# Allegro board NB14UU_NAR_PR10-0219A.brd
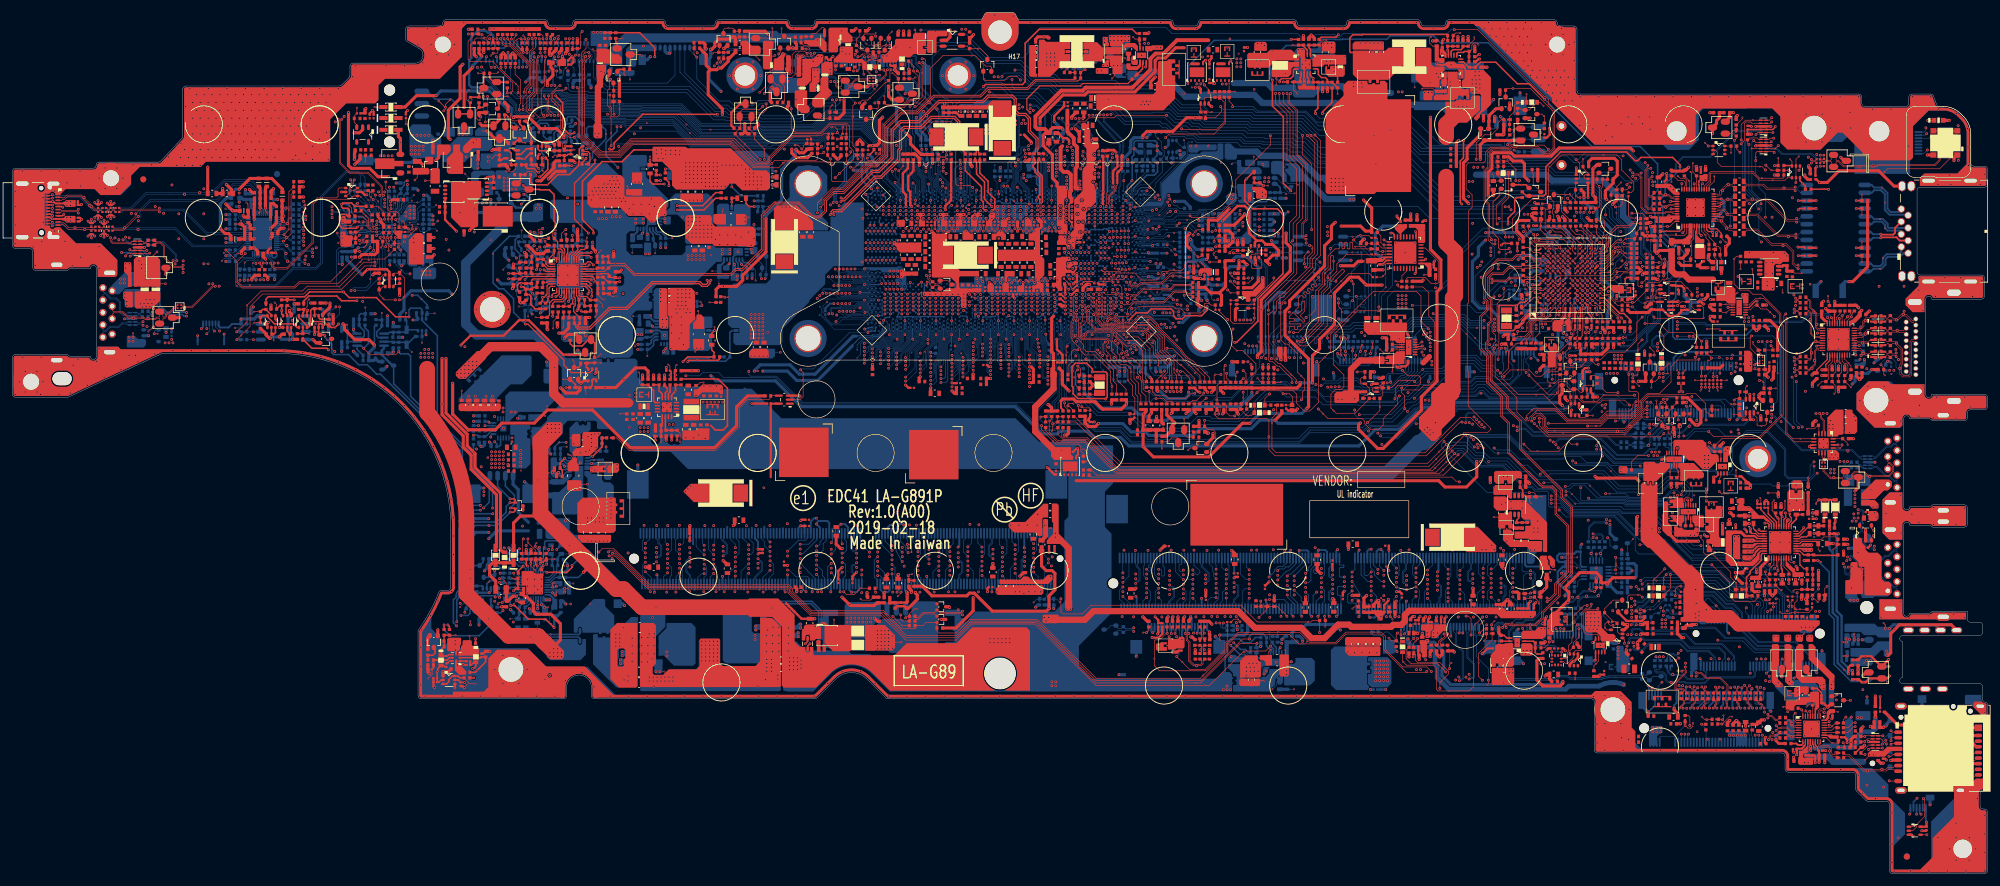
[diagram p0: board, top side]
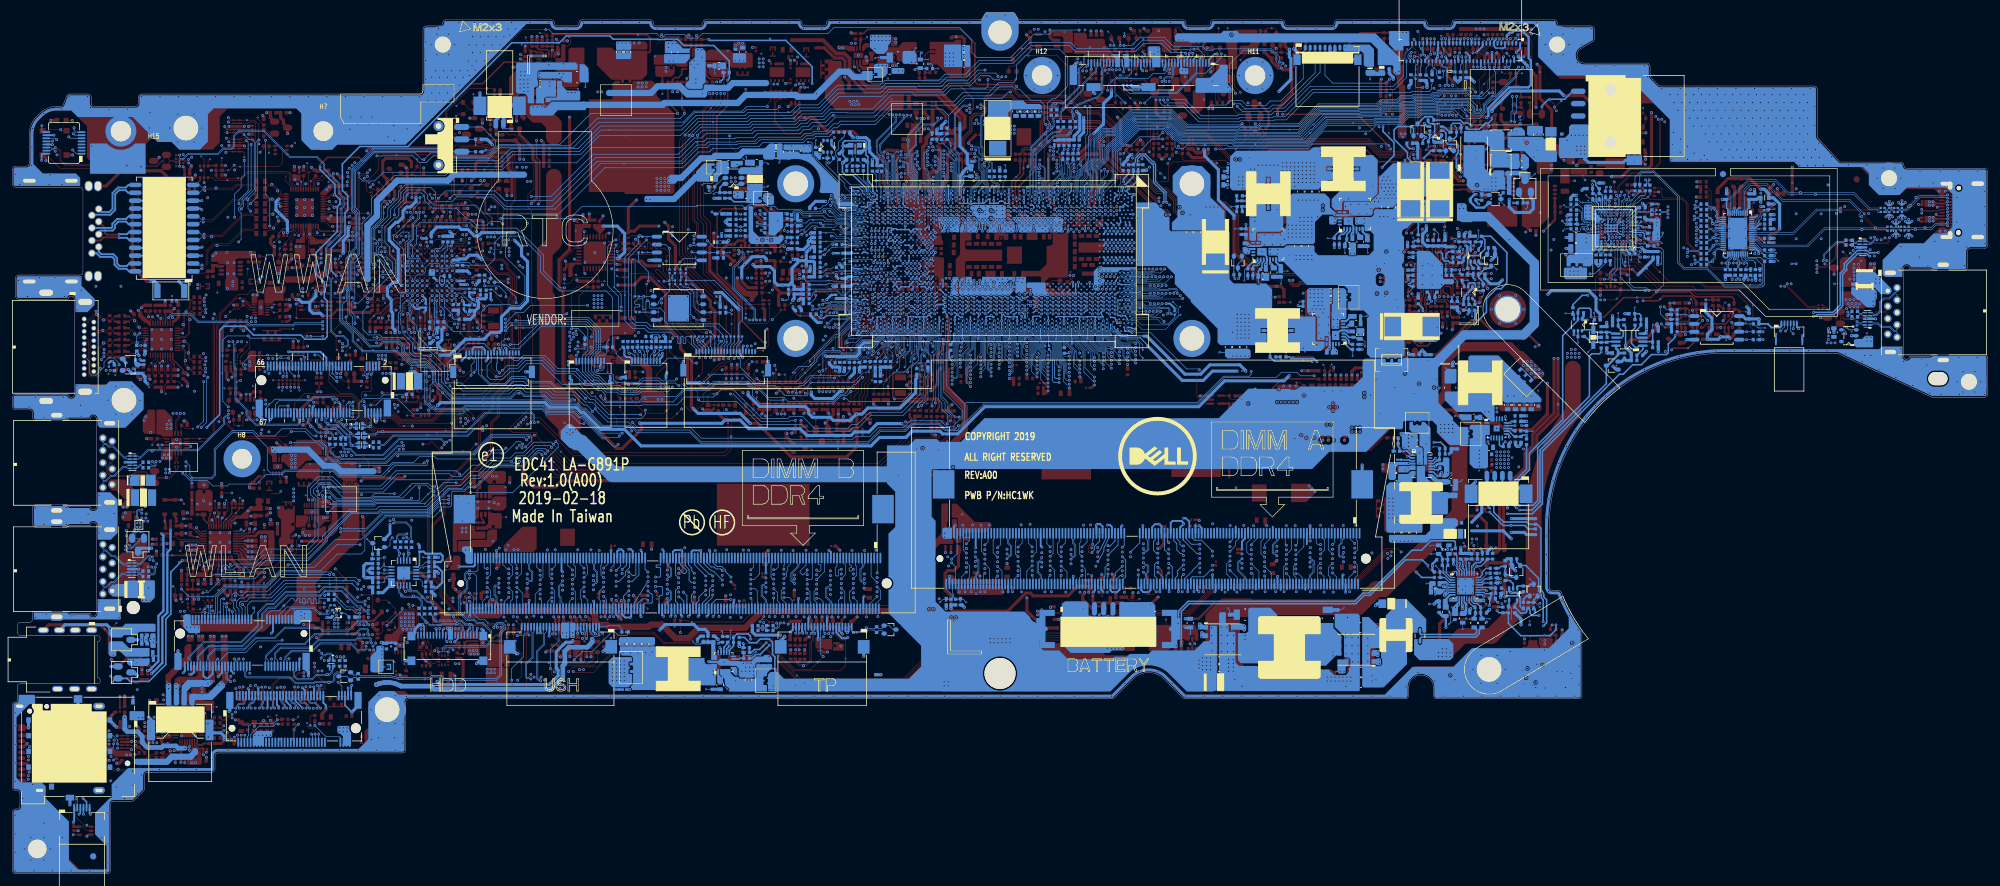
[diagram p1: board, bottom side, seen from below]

Outline 319.05 x 139.2 mm; copper layers: TOP, GND1, IN1, VCC, IN2, IN3, GND2, BOTTOM. Coordinates in mm from the lower left corner of the outline.

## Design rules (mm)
net group BC_CLK_ECE1117: nets BC_CLK_ECE1117 BC_DAT_ECE1117
net group CLK_TP_SIO_R: nets CLK_TP_SIO_R DAT_TP_SIO_R
net group CPU_DDPD_CTRL_CLK: nets CPU_DDPD_CTRL_CLK CPU_DDPD_CTRL_DATA
net group CPU_DP1_CTRL_CLK: nets CPU_DP1_CTRL_CLK CPU_DP1_CTRL_DATA
net group CPU_DP2_CTRL_CLK: nets CPU_DP2_CTRL_CLK CPU_DP2_CTRL_DATA
net group CPU_DP3_AUX: nets CPU_DP3_AUXN CPU_DP3_AUXP
net group CSI_ISL9538: nets CSIN_CHG CSIP_CHG
net group CSO_ISL9538: nets CSON_CHG CSOP_CHG
net group DDR_RESET: nets DDR_DRAMRST# DDR_DRAMRST#_R
net group DDRA_CKE: nets DDR_A_CKE0 DDR_A_CKE1
net group DDRALERT_10/10.5_20: nets DDR_A_ALERT# DDR_B_ALERT#
net group DIFFPAIR8: nets SML1_SMBCLK SML1_SMBDATA
net group DIFFPAIR9: nets MEM_SMBCLK MEM_SMBDATA
net group ESPI_CLK: nets ESPI_CLK ESPI_CLK_5105
net group HDMI_CLK_C: nets HDMI_CLKN_C HDMI_CLKP_C
net group HDMI_SCL_SINK: nets HDMI_SCL_SINK HDMI_SDA_SINK
net group HDMI_TX_0_C: nets HDMI_TX_N0_C HDMI_TX_P0_C
net group HDMI_TX_1_C: nets HDMI_TX_N1_C HDMI_TX_P1_C
net group HDMI_TX_2_C: nets HDMI_TX_N2_C HDMI_TX_P2_C
net group I2C1_SCK_TP: nets I2C1_SCK_TP I2C1_SDA_TP
net group ISH_I2C0_ACC_SCL: nets ISH_I2C0_ACC_SCL ISH_I2C1_ALS_SDA
net group PCIE_PRX_C_DTX_N12: nets PCIE_PRX_C_DTX_N12 PCIE_PRX_C_DTX_P12
net group PCIE_PTX_C_DRX_8: nets PCIE_PTX_C_DRX_N12 PCIE_PTX_C_DRX_P12
net group PCIE_PTX_DRX_12: nets PCIE_PTX_DRX_N12 PCIE_PTX_DRX_P12
net group PECI: nets PECI_EC PECI_EC_R
net group SATA_PRX_DTX_11: nets SATA_PRX_DTX_N11 SATA_PRX_DTX_P11
net group SATA_PTX_DRX_11: nets SATA_PTX_DRX_N11 SATA_PTX_DRX_P11
net group SD/MMCDAT0/RCLK: nets SD/MMCDAT0/RCLK+ SD/MMCDAT1/RCLK-
net group SD/MMCDAT0/RCLK+_R: nets SD/MMCDAT0/RCLK+_R SD/MMCDAT1/RCLK-_R
net group SD_UHS2_D0N: nets SD_UHS2_D0N SD_UHS2_D0P
net group SD_UHS2_D1N: nets SD_UHS2_D1N SD_UHS2_D1P
net group SML0_SMBCLK: nets SML0_SMBCLK SML0_SMBDATA
net group UART: nets UART_MISO UART_MOSI
net group VCC_SENSE_GT: nets VCC_SENSE_GT VSS_SENSE_GT
net group VCC_SENSE_IA: nets VCC_SENSE_IA VSS_SENSE_IA
net group VCC_SENSE_SA: nets VCC_SENSE_SA VSS_SENSE_SA
net group 5: nets ISH_I2C2_SCL ISH_I2C2_SCL_R ISH_I2C2_SDA ISH_I2C2_SDA_R ISH_UART0_CTS#_R ISH_UART0_RXD_R ISH_UART0_TXD_R PCH_3.3V_TS_EN PCH_BATLOW# PCH_CL_CLK1 PCH_CL_DATA1 PCH_CL_RST1# PCH_PRIM_EN PCH_RTCX1 PCH_RTCX2 PCH_RTCX2_R PCH_SPI_CS#0 PCH_SPI_CS#0_R1 PCH_SPI_CS#0_R2 PCH_SPI_CS#1 PCH_SPI_CS#1_R1 PCH_SPI_CS#1_R2 PCH_SPI_CS#2 PCH_SPI_CS#2_R PCH_SPI_D0 PCH_SPI_D0_0_R PCH_SPI_D0_1_R PCH_SPI_D0_2_R PCH_SPI_D0_R1 PCH_SPI_D1 PCH_SPI_D1_0_R PCH_SPI_D1_1_R PCH_SPI_D1_2_R PCH_SPI_D1_R1 PCH_SPI_D2 PCH_SPI_D2_0_R PCH_SPI_D2_1_R PCH_SPI_D2_R1 PCH_SPI_D3 PCH_SPI_D3_0_R PCH_SPI_D3_1_R PCH_SPI_D3_R1
net group 10: nets +MIC2-VREFO RING2 RING2_R SLEEVE SLEEVE_R
net group 12: nets EMMC_RCOMP PCIE_RCOMPN PCIE_RCOMPP
net group 15: nets SRTCRST# UIM_CLK UIM_DATA UIM_RESET UPD1_SMBINT# USBCOMP
net group 20: nets MEC_XTAL1 MEC_XTAL2 MEC_XTAL2_R XTALI XTALO XTALO_R
net group ASYNCHRONOUS: nets +DDR_VREF_A_CA +DDR_VREF_B_CA CFG_RCOMP CPU_POPIRCOMP EDRAM_OPIO_RCOMP H_CATERR# H_CPUPWRGD H_CPUPWRGD_R JDIMM1_EVENT# JDIMM2_EVENT# PCH_PLTRST# PCH_PLTRST#_AND PLTRST_LAN# PLTRST_TPM# PROCHOT# PROCHOT#_CHG PROCHOT#_R PROCHOT#_R1 SM_RCOMP0 SM_RCOMP1 SM_RCOMP2 VCCST_PWRGD VCCST_PWRGD_CPU VRALERT# XDP_OBS0 XDP_OBS0_R XDP_OBS1 XDP_OBS1_R
net group CARD READER: nets SD/MMCCD# SD/MMCCLK SD/MMCCLK_R SD/MMCCMD SD/MMCCMD_R SD/MMCDAT2 SD/MMCDAT2_R SD/MMCDAT3 SD/MMCDAT3_R SDWP
net group CNVI: nets CLK_CNV_PRX_DTX_N CLK_CNV_PRX_DTX_P CLK_CNV_PTX_DRX_N CLK_CNV_PTX_DRX_P CNV_PRX_DTX_N0 CNV_PRX_DTX_N1 CNV_PRX_DTX_P0 CNV_PRX_DTX_P1 CNV_PTX_DRX_N0 CNV_PTX_DRX_N1 CNV_PTX_DRX_P0 CNV_PTX_DRX_P1
net group CNVI_S: nets CNV_BRI_PRX_DTX CNV_BRI_PRX_DTX_R CNV_BRI_PTX_DRX CNV_BRI_PTX_DRX_R CNV_RGI_PRX_DTX CNV_RGI_PRX_DTX_R CNV_RGI_PTX_DRX CNV_RGI_PTX_DRX_R
net group CODEC: nets +LINE1-VREFO-L +LINE1-VREFO-R AUD_HP_NB_SENSE AUD_HP_OUT_L AUD_HP_OUT_L1 AUD_HP_OUT_R AUD_HP_OUT_R1 AUD_SENSE_A HP_OUT_L HP_OUT_R LINE1-VREFO LINE1_L LINE1_R
net group CRITICAL LOW SIGNAL: nets H_THERMTRIP# H_THERMTRIP#_R H_VCCST_PWRGD_XDP INTRUDER# LAN_WAKE# PCH_DPWROK PCH_DPWROK_EC PCH_PCIE_WAKE# PCH_PWROK PCH_RSMRST# PCH_RSMRST#_AND PCIE_WAKE# PCIE_WAKE#_R RESET_OUT RESET_OUT#_R SIO_PWRBTN# SYS_PWROK SYS_RESET# XDP_DBRESET#
net group CRITICAL LOW SPEED SIGNAL: nets PCH_RTCRST#
net group DDRA_D0: nets DDR_A_D0 DDR_A_D1 DDR_A_D2 DDR_A_D3 DDR_A_D4 DDR_A_D5 DDR_A_D6 DDR_A_D7
net group DDRA_D1: nets DDR_A_D8 DDR_A_D9 DDR_A_D10 DDR_A_D11 DDR_A_D12 DDR_A_D13 DDR_A_D14 DDR_A_D15
net group DDRA_D2: nets DDR_A_D16 DDR_A_D17 DDR_A_D18 DDR_A_D19 DDR_A_D20 DDR_A_D21 DDR_A_D22 DDR_A_D23
net group DDRA_D3: nets DDR_A_D24 DDR_A_D25 DDR_A_D26 DDR_A_D27 DDR_A_D28 DDR_A_D29 DDR_A_D30 DDR_A_D31
net group DDRA_D4: nets DDR_A_D32 DDR_A_D33 DDR_A_D34 DDR_A_D35 DDR_A_D36 DDR_A_D37 DDR_A_D38 DDR_A_D39
net group DDRA_D5: nets DDR_A_D40 DDR_A_D41 DDR_A_D42 DDR_A_D43 DDR_A_D44 DDR_A_D45 DDR_A_D46 DDR_A_D47
net group DDRA_D6: nets DDR_A_D48 DDR_A_D49 DDR_A_D50 DDR_A_D51 DDR_A_D52 DDR_A_D53 DDR_A_D54 DDR_A_D55
net group DDRA_D7: nets DDR_A_D56 DDR_A_D57 DDR_A_D58 DDR_A_D59 DDR_A_D60 DDR_A_D61 DDR_A_D62 DDR_A_D63
net group DDRB_D0: nets DDR_B_D0 DDR_B_D1 DDR_B_D2 DDR_B_D3 DDR_B_D4 DDR_B_D5 DDR_B_D6 DDR_B_D7
net group DDRB_D1: nets DDR_B_D8 DDR_B_D9 DDR_B_D10 DDR_B_D11 DDR_B_D12 DDR_B_D13 DDR_B_D14 DDR_B_D15
net group DDRB_D2: nets DDR_B_D16 DDR_B_D17 DDR_B_D18 DDR_B_D19 DDR_B_D20 DDR_B_D21 DDR_B_D22 DDR_B_D23
net group DDRB_D3: nets DDR_B_D24 DDR_B_D25 DDR_B_D26 DDR_B_D27 DDR_B_D28 DDR_B_D29 DDR_B_D30 DDR_B_D31
net group DDRB_D4: nets DDR_B_D32 DDR_B_D33 DDR_B_D34 DDR_B_D35 DDR_B_D36 DDR_B_D37 DDR_B_D38 DDR_B_D39
net group DDRB_D5: nets DDR_B_D40 DDR_B_D41 DDR_B_D42 DDR_B_D43 DDR_B_D44 DDR_B_D45 DDR_B_D46 DDR_B_D47
net group DDRB_D6: nets DDR_B_D48 DDR_B_D49 DDR_B_D50 DDR_B_D51 DDR_B_D52 DDR_B_D53 DDR_B_D54 DDR_B_D55
net group DDRB_D7: nets DDR_B_D56 DDR_B_D57 DDR_B_D58 DDR_B_D59 DDR_B_D60 DDR_B_D61 DDR_B_D62 DDR_B_D63
net group DDRCKE_10/10.5_20: nets DDR_A_CKE2 DDR_A_CKE3 DDR_B_CKE0 DDR_B_CKE1
net group DDRCLK_20: nets DDR_A_CLK0 DDR_A_CLK1 DDR_A_CLK#0 DDR_A_CLK#1 DDR_B_CLK0 DDR_B_CLK1 DDR_B_CLK#0 DDR_B_CLK#1
net group DDRCMD_10/10.5_20: nets DDR_A_ACT# DDR_A_BA0 DDR_A_BA1 DDR_A_BG0 DDR_A_BG1 DDR_A_MA0 DDR_A_MA1 DDR_A_MA2 DDR_A_MA3 DDR_A_MA4 DDR_A_MA5 DDR_A_MA6 DDR_A_MA7 DDR_A_MA8 DDR_A_MA9 DDR_A_MA10 DDR_A_MA11 DDR_A_MA12 DDR_A_MA13 DDR_A_MA14 DDR_A_MA15 DDR_A_MA16 DDR_A_PARITY DDR_B_ACT# DDR_B_BA0 DDR_B_BA1 DDR_B_BG0 DDR_B_BG1 DDR_B_MA0 DDR_B_MA1 DDR_B_MA2 DDR_B_MA3 DDR_B_MA4 DDR_B_MA5 DDR_B_MA6 DDR_B_MA7 DDR_B_MA8 DDR_B_MA9 DDR_B_MA10 DDR_B_MA11 DDR_B_MA12 DDR_B_MA13 DDR_B_MA14 DDR_B_MA15 DDR_B_MA16 DDR_B_PARITY
net group DDRCTL_10/10.5_20: nets DDR_A_CS#0 DDR_A_CS#1 DDR_A_ODT0 DDR_A_ODT1 DDR_B_CS#0 DDR_B_CS#1 DDR_B_ODT0 DDR_B_ODT1
net group DDRDQS_19/16_20: nets DDR_A_DQS0 DDR_A_DQS1 DDR_A_DQS2 DDR_A_DQS3 DDR_A_DQS4 DDR_A_DQS5 DDR_A_DQS6 DDR_A_DQS7 DDR_A_DQS#0 DDR_A_DQS#1 DDR_A_DQS#2 DDR_A_DQS#3 DDR_A_DQS#4 DDR_A_DQS#5 DDR_A_DQS#6 DDR_A_DQS#7 DDR_B_DQS0 DDR_B_DQS1 DDR_B_DQS2 DDR_B_DQS3 DDR_B_DQS4 DDR_B_DQS5 DDR_B_DQS6 DDR_B_DQS7 DDR_B_DQS#0 DDR_B_DQS#1 DDR_B_DQS#2 DDR_B_DQS#3 DDR_B_DQS#4 DDR_B_DQS#5 DDR_B_DQS#6 DDR_B_DQS#7
net group DP: nets CPU_DP1_N0 CPU_DP1_N1 CPU_DP1_N2 CPU_DP1_N3 CPU_DP1_P0 CPU_DP1_P1 CPU_DP1_P2 CPU_DP1_P3 CPU_DP2_AUXN CPU_DP2_AUXN_C CPU_DP2_AUXN_C_MUX CPU_DP2_AUXP CPU_DP2_AUXP_C CPU_DP2_AUXP_C_MUX CPU_DP2_N0 CPU_DP2_N0_C CPU_DP2_N1 CPU_DP2_N1_C CPU_DP2_N2 CPU_DP2_N2_C CPU_DP2_N3 CPU_DP2_N3_C CPU_DP2_P0 CPU_DP2_P0_C CPU_DP2_P1 CPU_DP2_P1_C CPU_DP2_P2 CPU_DP2_P2_C CPU_DP2_P3 CPU_DP2_P3_C
net group EDP: nets EDP_AUXN EDP_AUXN_C EDP_AUXP EDP_AUXP_C EDP_TXN0 EDP_TXN0_C EDP_TXN1 EDP_TXN1_C EDP_TXP0 EDP_TXP0_C EDP_TXP1 EDP_TXP1_C
net group ESPI: nets ESPI_ALERT# ESPI_CS# ESPI_IO0 ESPI_IO0_R ESPI_IO1 ESPI_IO1_R ESPI_IO2 ESPI_IO2_R ESPI_IO3 ESPI_IO3_R ESPI_RESET#
net group HDA: nets DMIC0 HDA_RST# HDA_RST#_R HDA_SDIN0 HDA_SDIN0_R HDA_SDOUT HDA_SDOUT_R HDA_SYNC HDA_SYNC_R
net group HDMI: nets TMDSE_CON_CLK TMDSE_CON_CLK# TMDSE_CON_N0 TMDSE_CON_N1 TMDSE_CON_N2 TMDSE_CON_P0 TMDSE_CON_P1 TMDSE_CON_P2 TMDSE_RP_CLK TMDSE_RP_CLK# TMDSE_RP_N0 TMDSE_RP_N1 TMDSE_RP_N2 TMDSE_RP_P0 TMDSE_RP_P1 TMDSE_RP_P2
net group MDI-LAN: nets RJ45_MDIN0 RJ45_MDIN1 RJ45_MDIN2 RJ45_MDIN3 RJ45_MDIP0 RJ45_MDIP1 RJ45_MDIP2 RJ45_MDIP3
net group MDI-LAN-SW: nets LAN_MDIN0 LAN_MDIN0_L LAN_MDIN1 LAN_MDIN1_L LAN_MDIN2 LAN_MDIN2_L LAN_MDIN3 LAN_MDIN3_L LAN_MDIP0 LAN_MDIP0_L LAN_MDIP1 LAN_MDIP1_L LAN_MDIP2 LAN_MDIP2_L LAN_MDIP3 LAN_MDIP3_L
net group OTHERS SINGLE-END: nets BAT1_LED# BAT2_LED# BATT_WHITE# BATT_YELLOW#
net group PCIE: nets PCIE_PRX_C_DTX_N8 PCIE_PRX_C_DTX_N9 PCIE_PRX_C_DTX_N13 PCIE_PRX_C_DTX_N14 PCIE_PRX_C_DTX_N15 PCIE_PRX_C_DTX_N16 PCIE_PRX_C_DTX_P8 PCIE_PRX_C_DTX_P9 PCIE_PRX_C_DTX_P13 PCIE_PRX_C_DTX_P14 PCIE_PRX_C_DTX_P15 PCIE_PRX_C_DTX_P16 PCIE_PRX_DTX_N8 PCIE_PRX_DTX_N9 PCIE_PRX_DTX_N10 PCIE_PRX_DTX_N12 PCIE_PRX_DTX_N13 PCIE_PRX_DTX_N14 PCIE_PRX_DTX_N15 PCIE_PRX_DTX_N16 PCIE_PRX_DTX_P8 PCIE_PRX_DTX_P9 PCIE_PRX_DTX_P10 PCIE_PRX_DTX_P12 PCIE_PRX_DTX_P13 PCIE_PRX_DTX_P14 PCIE_PRX_DTX_P15 PCIE_PRX_DTX_P16 PCIE_PTX_C_DRX_N8 PCIE_PTX_C_DRX_N9 PCIE_PTX_C_DRX_N10 PCIE_PTX_C_DRX_N13 PCIE_PTX_C_DRX_N14 PCIE_PTX_C_DRX_N15 PCIE_PTX_C_DRX_N16 PCIE_PTX_C_DRX_P8 PCIE_PTX_C_DRX_P9 PCIE_PTX_C_DRX_P10 PCIE_PTX_C_DRX_P13 PCIE_PTX_C_DRX_P14 PCIE_PTX_C_DRX_P15 PCIE_PTX_C_DRX_P16 PCIE_PTX_DRX_N8 PCIE_PTX_DRX_N9 PCIE_PTX_DRX_N10 PCIE_PTX_DRX_N13 PCIE_PTX_DRX_N14 PCIE_PTX_DRX_N15 PCIE_PTX_DRX_N16 PCIE_PTX_DRX_P8 PCIE_PTX_DRX_P9 PCIE_PTX_DRX_P10 PCIE_PTX_DRX_P13 PCIE_PTX_DRX_P14 PCIE_PTX_DRX_P15 PCIE_PTX_DRX_P16
net group PLATFORM_CLK: nets CLK_ITPXDP_N CLK_ITPXDP_N_R CLK_ITPXDP_P CLK_ITPXDP_P_R CLK_PCIE_N0 CLK_PCIE_N1 CLK_PCIE_N2 CLK_PCIE_N3 CLK_PCIE_N4 CLK_PCIE_P0 CLK_PCIE_P1 CLK_PCIE_P2 CLK_PCIE_P3 CLK_PCIE_P4
net group RTC-RTCX: nets PCH_RTCX1_R RTCRST_ON RTCRST_ON_R RTCX2
net group SATA: nets SATA_PRX_C_DTX_N0 SATA_PRX_C_DTX_P0 SATA_PRX_C_RD_DTX_N11 SATA_PRX_C_RD_DTX_P11 SATA_PRX_RD_DTX_N0 SATA_PRX_RD_DTX_P0 SATA_PTX_C_DRX_N0 SATA_PTX_C_DRX_P0 SATA_PTX_C_RD_DRX_N11 SATA_PTX_C_RD_DRX_P11 SATA_PTX_RD_DRX_N0 SATA_PTX_RD_DRX_P0
net group SINGLE_CLOCK: nets CPU_XDP_TCLK DMIC_CLK0 DMIC_CLK_CODEC HDA_BIT_CLK HDA_BIT_CLK_R JTAG_CLK MSCLK REFCLK_CNV SUSCLK SUSCLK_R WIGIG_32KHZ XDP_JTAGX
net group SMBUS/I2C: nets BCM5882_ALERT# CLK_TP_SIO_I2C_DAT DAT_TP_SIO_I2C_CLK DDR_XDP_WAN_SMBCLK DDR_XDP_WAN_SMBDAT I2C1_SCK_TP_R I2C1_SDA_TP_R I2C2_SCL_ALS I2C2_SDA_ALS I2C3_ANT_SCL I2C3_ANT_SDA ISH_I2C0_ACC_SDA PBAT_CHARGER_SMBCLK PBAT_CHARGER_SMBDAT PBAT_SMBCLK_C PBAT_SMBDAT_C PCH_SMB_ALERT# PS8802_CSCL PS8802_CSDA SML0B_SMBCLK SML0B_SMBDATA TBTA_DEBUG1 TBTA_DEBUG2 TS_I2C_SCL TS_I2C_SDA UPD1_SMBCLK UPD1_SMBCLK_Q UPD1_SMBDAT UPD1_SMBDAT_Q UPD1_SMBUS_ALERT# UPD2_SMBCLK UPD2_SMBDAT USH_EXPANDER_SMBCLK USH_EXPANDER_SMBDAT
net group SPI: nets PCH_SPI_DO2_XDP PCH_SPI_DO_XDP TBTA_ROM_CS#_PD TBTA_ROM_DI_PD TBTA_ROM_DI_PD_R TBTA_ROM_DO_PD TBTA_ROM_DO_PD_R
net group SPI_CLK: nets PCH_SPI_CLK PCH_SPI_CLK_0_R PCH_SPI_CLK_1_R PCH_SPI_CLK_2_R PCH_SPI_CLK_R1 TBTA_ROM_CLK_PD TBTA_ROM_CLK_PD_R
net group SPK: nets INT_SPK_L+ INT_SPK_L- INT_SPK_R+ INT_SPK_R- INT_SPKR_L+ INT_SPKR_L- INT_SPKR_R+ INT_SPKR_R-
net group SVID: nets H_CPU_SVIDALRT# VIDALERT_N VIDSCLK VIDSCLK_R VIDSOUT VIDSOUT_R
net group THERMAL: nets REM_DIODE1_N REM_DIODE1_P REM_DIODE2_N REM_DIODE2_P REM_DIODE4_N REM_DIODE4_P
net group USB2.0: nets SW_USB20_N2 SW_USB20_P2 TBTA_BOT_N TBTA_BOT_N_R TBTA_BOT_P TBTA_BOT_P_R TBTA_TOP_N TBTA_TOP_N_R TBTA_TOP_P TBTA_TOP_P_R USB20_N1 USB20_N2 USB20_N2_R USB20_N3 USB20_N3_R USB20_N4 USB20_N4_R USB20_N6 USB20_N6_R USB20_N7 USB20_N7_L USB20_N8 USB20_N9 USB20_N9_FP USB20_N9_USH USB20_N10 USB20_N10_R USB20_P1 USB20_P2 USB20_P2_R USB20_P3 USB20_P3_R USB20_P4 USB20_P4_R USB20_P6 USB20_P6_R USB20_P7 USB20_P7_L USB20_P8 USB20_P9 USB20_P9_FP USB20_P9_USH USB20_P10 USB20_P10_R
net group USB3.0: nets USB3_PRX_DTX_N2 USB3_PRX_DTX_N3 USB3_PRX_DTX_N4 USB3_PRX_DTX_N5 USB3_PRX_DTX_P2 USB3_PRX_DTX_P3 USB3_PRX_DTX_P4 USB3_PRX_DTX_P5 USB3_PRX_L_DTX_N2 USB3_PRX_L_DTX_P2 USB3_PTX_C_DRX_N2 USB3_PTX_C_DRX_N3 USB3_PTX_C_DRX_N4 USB3_PTX_C_DRX_N5 USB3_PTX_C_DRX_P2 USB3_PTX_C_DRX_P3 USB3_PTX_C_DRX_P4 USB3_PTX_C_DRX_P5 USB3_PTX_DRX_N2 USB3_PTX_DRX_N3 USB3_PTX_DRX_N4 USB3_PTX_DRX_N5 USB3_PTX_DRX_P2 USB3_PTX_DRX_P3 USB3_PTX_DRX_P4 USB3_PTX_DRX_P5 USB3_PTX_L_DRX_N2 USB3_PTX_L_DRX_P2
net group USB3.1: nets USB3_PRX_C_MTX_N1 USB3_PRX_C_MTX_P1 USB3_PRX_MTX_N1 USB3_PRX_MTX_P1 USB3_PTX_C_MRX_N1 USB3_PTX_C_MRX_P1 USB3_PTX_MRX_N1 USB3_PTX_MRX_P1
net group USB_RETIMER: nets USB3_DP2_MRX_C_DTX_N0 USB3_DP2_MRX_C_DTX_N1 USB3_DP2_MRX_C_DTX_P0 USB3_DP2_MRX_C_DTX_P1 USB3_DP2_MRX_DTX_N0 USB3_DP2_MRX_DTX_N1 USB3_DP2_MRX_DTX_P0 USB3_DP2_MRX_DTX_P1 USB3_DP2_MRX_R_DTX_N0 USB3_DP2_MRX_R_DTX_N1 USB3_DP2_MRX_R_DTX_P0 USB3_DP2_MRX_R_DTX_P1 USB3_DP2_MTX_C_DRX_N0 USB3_DP2_MTX_C_DRX_N1 USB3_DP2_MTX_C_DRX_P0 USB3_DP2_MTX_C_DRX_P1 USB3_DP2_MTX_DRX_N0 USB3_DP2_MTX_DRX_N1 USB3_DP2_MTX_DRX_P0 USB3_DP2_MTX_DRX_P1 USB3_DP2_MTX_R_DRX_N0 USB3_DP2_MTX_R_DRX_N1 USB3_DP2_MTX_R_DRX_P0 USB3_DP2_MTX_R_DRX_P1
net group XTAL: nets XCLK_BIASREF XTAL24_IN XTAL24_IN_CPU XTAL24_OUT XTAL24_OUT_CPU XTAL24_OUT_R
nets with their own width: min track width 0.127; nets EDP_COMP
nets with their own width: min track width 0.254; nets BAT1_LED#_R BL_PWR_MONITOR N35854159 N35854224 N35854247
nets with their own width: min track width 0.381; nets CNV_WT_RCOMP EOPIO_RCOMP N25908122 PCH_POPIRCOMP SD_RCOMP
nets with their own width: min track width 0.508; nets +0.6VSP +1.0V_APLL +1.0V_CLK +1.0V_PRIM +1.0V_PRIM_XDP +1.0V_VCCST +1.0V_VCCST_C +1.0V_VCCSTG +1.0V_VCCSTG_C +1.0VS_VCCIO +1.2V_DDRP +1.2V_LDO +1.2V_MEM +1.2V_RUN +1.2V_VDD_A1 +1.2V_VDD_A2 +1.2V_VDD_DM_D1 +1.2V_VDD_R1 +1.2V_VDD_R2 +1.05VALWP +1.8V_RUN_AUDIO +1.8V_RUN_CARD +1.8V_RUN_UZ46 +1.8VALWP +3.3V_ALW +3.3V_ALW2 +3.3V_ALW_DSW +3.3V_ALW_PCH_U44 +3.3V_ALW_UE1 +3.3V_ALW_UZ12 +3.3V_ALWP +3.3V_CPS +3.3V_EC_PLL +3.3V_FPBTN +3.3V_HDD +3.3V_MMI_AUX +3.3V_RTC_LDO +3.3V_RUN_AUDIO +3.3V_RUN_AUDIO_DVDD +3.3V_RUN_AUDIO_IO +3.3V_RUN_AUDIO_UZ5 +3.3V_RUN_DIMM1 +3.3V_RUN_DIMM2 +3.3V_RUN_UT9 +3.3V_RUN_UZ44 +3.3V_SPI +3.3V_TBTA_FLASH +3.3V_TP +3.3V_VDD_DCIN +3.3V_VDD_PIC +3.3V_VPS_UZ12 +5V_ALW +5V_ALW2 +5V_ALWP +5V_PD_VDD +5V_RUN +5V_TBT_VBUS +5V_TBTA_VBUS_D +13.2VB_BATT +13.2VB_PBATT_C +13.5VB +13.5VB_3V +13.5VB_5V +13.5VB_DDR +13.5VB_IR +13.5VB_VCHGR +19.5V_AC +19.5V_CHARGER +19.5V_DC_IN +19.5V_DC_IN_SS +19.5V_DCIN_JACK +19.5V_SDC_IN +20V_TBTA_VBUS +20V_TBTA_VBUS_1 +20V_VBUS_DC_SS +BL_PWR_SRC_P +COINCELL +DDR_VREF_B_DQ +DDR_VREF_CA +DV33_18 +EC_DEBUG_VCC +GND_CHASSIS +RREF +RSVD_VCC3P3_1 +RTC_CELL +RTC_CELL_PCH +RTC_CELL_VBAT +SDREG2 +SIM_PWR +UZ12_TPM +VCC1V8A_TBTA_LDO +VCCDPHY_1P24 +VCCPDSW_1P05 +VCCPLL_OC +VDDA_AVDD1 +VR_CAP +VSS_PLL +Z4012 GND VCCHDA
nets with their own width: min track width 0.635; nets +1.0V_AMPHYPLL +1.0V_VCCST_R
nets with their own width: min track width 0.762; nets +1.8V_ALW_VTR3 +3.3V_VDD_PIC_R
nets with their own width: min track width 1.016; nets +0.6V_DDR_VTT +0.9V_LAN +1.8V_PRIM +1.8V_RUN +2.5V_MEM +3.3V_ALW_PCH +3.3V_CAM +3.3V_CAM_F +3.3V_LAN +3.3V_LAN_OUT +3.3V_RUN +3.3V_RUN_CARD +3.3V_RUN_F +3.3V_RUN_QZ1 +REGCTL_PNP10 +VHDMI_VCC
nets with their own width: min track width 1.27; nets +3.3V_MMI_IN
nets with their own width: min track width 1.524; nets +EDP_VDD +LCDVDD
nets with their own width: min track width 2.032; nets +5V_HDD +BL_PWR_SRC +USB_EX2_PWR +USB_EX3_PWR
nets with their own width: min track width 2.286; nets +3.3V_HDD_M2 +3.3V_WLAN
nets with their own width: min track width 2.54; nets +5V_RUN_AUDIO +5V_RUN_AUDIO_UZ5 +5V_RUN_PVDD_L +5V_USB_CHG_PWR
nets with their own width: min track width 2.794; nets +1.0V_PRIM_CORE +3.3V_WWAN +3.3V_WWAN_UZ43
nets with their own width: min track width 3.048; nets +1.0V_MPHYGT
nets with their own width: min track width 3.556; nets +5V_ALW_PDA

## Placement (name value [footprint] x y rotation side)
CA1  220P_0402_50V7K  [C_0402]  297.26 39.46 270 bottom
CA2  680P_0402_50V7K  [C_0402]  298.13 33.65 90 top
CA3  680P_0402_50V7K  [C_0402]  298.13 32.28 270 top
CA4  220P_0402_50V7K  [C_0402]  297.26 36.19 90 bottom
CA5  100P_0402_50V8J  [C_0402]  124.46 124.65 0 top
CA6  82P_0402_50V8J  [C_0402]  123.55 124.64 180 top
CA7  0.1U_0201_10V6K  [C_0201]  132.22 130.95 90 top
CA8  0.1U_0201_10V6K  [C_0201]  290.22 57.35 0 top
CA9  10U_0603_10V6M  [C_0603]  290.06 58.3 0 top
CA10  0.1U_0201_10V6K  [C_0201]  282.29 48.59 180 top
CA12  680P_0402_50V7K  [C_0402]  298.15 39.46 270 bottom
CA13  680P_0402_50V7K  [C_0402]  298.15 37.11 270 bottom
CA19  1000P_0402_50V7K  [C_0402]  279.73 51.13 180 top
CA22  1000P_0402_50V7K  [C_0402]  279.73 53.79 180 top
CA23  1000P_0402_50V7K  [C_0402]  279.73 52.91 180 top
CA24  1000P_0402_50V7K  [C_0402]  279.73 52.02 180 top
CA25  10U_0603_10V6M  [C_0603]  291.68 53.35 0 top
CA27  0.1U_0402_25V6  [C_0402]  290.77 49.29 180 top
CA28  0.1U_0402_25V6  [C_0402]  289.94 47.43 90 top
CA29  1U_0201_6.3V6K  [C_0201]  281.85 59.73 270 top
CA31  1U_0201_6.3V6M  [C_0201]  280.09 46.94 180 top
CA33  10P_0402_50V8J  [C_0402]  284.79 46.63 270 top
CA35  2.2U_0201_6.3V6M  [C_0201]  287.08 58.16 90 top
CA41  0.1U_0402_25V6  [C_0402]  290.06 51.52 270 top
CA43  10U_0603_10V6M  [C_0603]  290.32 56.21 0 top
CA44  10U_0603_10V6M  [C_0603]  290.32 54.94 0 top
CA45  0.1U_0201_10V6K  [C_0201]  278.35 55.28 90 top
CA46  10U_0603_10V6M  [C_0603]  279.33 50.05 270 top
CA47  0.1U_0201_10V6K  [C_0201]  280.22 49.9 270 top
CA48  10U_0603_10V6M  [C_0603]  277.3 55.13 90 top
CA51  10U_0603_10V6M  [C_0603]  288.16 58.05 90 top
CA52  10U_0603_10V6M  [C_0603]  281.24 56.59 180 top
CA53  10U_0603_10V6M  [C_0603]  285.87 48.27 270 top
CA54  100P_0402_50V8J  [C_0402]  283.84 46.63 270 top
CA55  0.1U_0201_10V6K  [C_0201]  287.74 49.1 0 top
CA56  10U_0603_10V6M  [C_0603]  288.03 48.27 270 top
CA57  0.1U_0201_10V6K  [C_0201]  280.74 55.19 180 top
CA58  10U_0603_10V6M  [C_0603]  281.24 57.8 180 top
CA59  10U_0603_10V6M  [C_0603]  274.12 53.67 270 top
CA60  0.1U_0201_10V6K  [C_0201]  274.42 54.49 180 top
CA61  10U_0603_10V6M  [C_0603]  282 47.84 270 top
CA62  100P_0402_50V8J  [C_0402]  289.94 45.93 270 top
CA63  12P_0402_50V8J  [C_0402]  275.32 55.83 0 top
CA64  68P_0402_50V8J  [C_0402]  275.32 54.94 0 top
CA65  12P_0402_50V8J  [C_0402]  279.13 62.3 0 top
CA66  68P_0402_50V8J  [C_0402]  279.13 63.19 0 top
CA67  12P_0402_50V8J  [C_0402]  267.76 54.94 0 top
CA68  68P_0402_50V8J  [C_0402]  267.76 55.83 0 top
CA69  33P_0402_50V8J  [C_0402]  278.9 59.07 180 top
CA72  100P_0402_50V8J  [C_0402]  290.81 48.33 0 top
CA73  330P_0402_50V8J  [C_0402]  284.79 58.29 90 top
CA74  330P_0402_50V8J  [C_0402]  285.68 58.29 90 top
CA75  100P_0402_50V8J  [C_0402]  131.47 130.96 90 top
CA76  1U_0201_6.3V6K  [C_0201]  282.42 59.73 270 top
CA77  1U_0201_6.3V6K  [C_0201]  283 59.14 90 top
CA78  1U_0201_6.3V6K  [C_0201]  283.6 59.14 90 top
CC9  0.1U_0201_10V6K  [C_0201]  205.33 93.29 180 bottom
CC10  0.1U_0201_10V6K  [C_0201]  205.08 102.94 180 bottom
CC21  15P_0402_50V8J  [C_0402]  183.37 115.39 0 bottom
CC22  15P_0402_50V8J  [C_0402]  182.51 115.39 180 bottom
CC23  15P_0402_50V8J  [C_0402]  174.02 77.49 90 top
CC24  1U_0201_6.3V6M  [C_0201]  174.09 74.84 270 top
CC25  1U_0201_6.3V6M  [C_0201]  205.73 75.74 270 top
CC26  15P_0402_50V8J  [C_0402]  174.02 80.43 270 top
CC27  47P_0402_50V8J  [C_0402]  170.59 73 270 top
CC28  1U_0201_6.3V6M  [C_0201]  169.3 103.55 270 top
CC29  1U_0201_6.3V6M  [C_0201]  164.8 115.09 180 bottom
CC31  1U_0201_6.3V6M  [C_0201]  169.73 118.3 90 top
CC32  22U_0603_6.3V6M  [C_0603]  149.7 77.62 180 top
CC33  10U_0402_6.3V6M  [C_0402]  156.42 80.04 0 top
CC34  10U_0402_6.3V6M  [C_0402]  156.42 79.09 0 top
CC35  10U_0402_6.3V6M  [C_0402]  165.84 79.47 180 top
CC36  10U_0402_6.3V6M  [C_0402]  167.48 85.51 270 bottom
CC37  10U_0402_6.3V6M  [C_0402]  149.13 85.02 270 bottom
CC38  10U_0402_6.3V6M  [C_0402]  165.84 80.42 180 top
CC39  10U_0402_6.3V6M  [C_0402]  167.19 94.27 180 top
CC40  10U_0402_6.3V6M  [C_0402]  167.19 95.16 180 top
CC41  10U_0402_6.3V6M  [C_0402]  111.69 77.21 90 top
CC42  10U_0402_6.3V6M  [C_0402]  153.47 95.15 270 top
CC45  10U_0402_6.3V6M  [C_0402]  153.4 78.51 180 top
CC46  10U_0402_6.3V6M  [C_0402]  153.4 77.62 180 top
CC51  10U_0402_6.3V6M  [C_0402]  113.72 77.21 90 top
CC52  10U_0402_6.3V6M  [C_0402]  169.92 101.03 90 top
CC65  1U_0201_6.3V6M  [C_0201]  174.77 95.4 0 top
CC66  1U_0201_6.3V6M  [C_0201]  173.07 102.04 180 top
CC67  1U_0201_6.3V6M  [C_0201]  171.85 98.61 270 top
CC68  1U_0201_6.3V6M  [C_0201]  170.6 98.08 180 top
CC69  1U_0201_6.3V6M  [C_0201]  170.47 124.65 180 top
CC70  1U_0201_6.3V6M  [C_0201]  190.54 116.15 90 bottom
CC71  22U_0603_6.3V6M  [C_0603]  185.29 127.2 180 top
CC72  0.1U_0201_6.3V6K  [C_0201]  170.59 96.7 90 top
CC73  1U_0201_6.3V6M  [C_0201]  173.26 73.23 0 top
CC75  1U_0201_6.3V6M  [C_0201]  185.99 92.96 90 bottom
CC76  1U_0201_6.3V6M  [C_0201]  169.86 96.17 90 top
CC77  2.2P_0201_25V  [C_0201]  193.14 96.09 180 top
CC78  0.1U_0402_25V6  [C_0402]  193.16 101.94 270 bottom
CC80  1U_0201_6.3V6M  [C_0201]  170.47 124.04 180 top
CC83  1U_0201_6.3V6M  [C_0201]  191.19 116.15 90 bottom
CC84  4.7U_0402_6.3V6M  [C_0402]  185.02 94.94 0 bottom
CC85  22U_0603_6.3V6M  [C_0603]  173.73 118.53 180 top
CC86  22U_0603_6.3V6M  [C_0603]  173.73 119.73 180 top
CC93  0.1U 16V K X5R 0201  [C_0201]  181.22 73.7 90 top
CC95  2.2P_0201_25V  [C_0201]  192.55 96.78 90 top
CC96  22U_0603_6.3V6M  [C_0603]  168.63 118.3 90 top
CC98  1U_0201_6.3V6M  [C_0201]  185.02 100.28 0 bottom
CC100  22U_0603_6.3V6M  [C_0603]  192.34 116.09 90 bottom
CC102  22U_0603_6.3V6M  [C_0603]  173.07 124.45 270 top
CC103  22U_0603_6.3V6M  [C_0603]  193.99 115.99 90 bottom
CC104  22U_0603_6.3V6M  [C_0603]  171.82 124.43 270 top
CC195  1U_0201_6.3V6M  [C_0201]  145.61 78.51 180 top
CC196  .047U_0402_16V7K  [C_0402]  218.49 81.1 0 top
CC234  10U_0402_6.3V6M  [C_0402]  112.71 77.21 90 top
CC235  10U_0402_6.3V6M  [C_0402]  169.03 101.03 90 top
CC236  10U_0402_6.3V6M  [C_0402]  169.03 100.19 270 top
CC237  10U_0402_6.3V6M  [C_0402]  154.43 95.15 270 top
CC266  0.01UF_0402_25V7K  [C_0402]  192.82 75.92 270 top
CC269  0.1U_0402_25V6  [C_0402]  87.82 134.26 270 top
CC279  22U_0603_6.3V6M  [C_0603]  184.82 71.72 90 top
CC280  22U_0603_6.3V6M  [C_0603]  183.61 71.72 90 top
CC288  0.1U_0201_10V6K  [C_0201]  89.19 130.78 0 top
CC299  0.1U_0201_10V6K  [C_0201]  89.19 131.42 0 top
CC300  100P_0402_50V8J  [C_0402]  159.57 112.65 90 bottom
CC301  100P_0402_50V8J  [C_0402]  168.07 120.47 0 bottom
CC302  0.1U_0402_25V6  [C_0402]  192.27 101.94 270 bottom
CC303  0.1U_0402_25V6  [C_0402]  131.68 116.15 0 top
CC304  0.1U_0402_25V6  [C_0402]  134.75 116.15 180 top
CC305  0.1U_0402_25V6  [C_0402]  137.35 116.96 90 top
CC306  0.1U_0402_25V6  [C_0402]  91.64 129.12 270 bottom
CC307  0.1U_0402_25V6  [C_0402]  86.93 134.26 270 top
CC308  0.1U_0402_25V6  [C_0402]  93.15 129.12 270 bottom
CC316  33P_0402_50V8J  [C_0402]  184.06 78.59 90 top
CC318  33P_0402_50V8J  [C_0402]  194.96 104.8 0 top
CC319  33P_0402_50V8J  [C_0402]  188.58 99.64 0 bottom
CC320  33P_0402_50V8J  [C_0402]  197.9 100.73 90 top
CC322  2.2P_0402_50V8C  [C_0402]  168.17 81.67 0 top
CC326  0.1U_0402_25V6  [C_0402]  90.71 129.06 270 bottom
CC331  2.2P_0402_50V8C  [C_0402]  166.91 73.87 90 top
CC332  2.2P_0402_50V8C  [C_0402]  167.86 73.87 90 top
CC333  2.2P_0402_50V8C  [C_0402]  168.82 73.87 90 top
CC334  0.1U_0402_25V6  [C_0402]  89.59 134.26 270 top
CC340  0.1U_0402_25V6K  [C_0402]  191.66 71.4 0 top
CC430  1U_0201_6.3V6M  [C_0201]  168.21 94.3 90 top
CC1452  33P_0402_50V8J  [C_0402]  204.2 99.51 0 bottom
CC1453  33P_0402_50V8J  [C_0402]  203.82 91.54 0 bottom
CC1454  10U_0402_6.3V6M  [C_0402]  147.38 79.53 180 top
CC1455  1U_0201_6.3V6M  [C_0201]  153.11 79.28 180 top
CC1456  1U_0201_6.3V6M  [C_0201]  156.84 82.2 0 top
CC1457  1U_0201_6.3V6M  [C_0201]  151.61 85.32 270 bottom
CC1458  1U_0201_6.3V6M  [C_0201]  114.49 77.12 90 top
CC1459  1U_0201_6.3V6M  [C_0201]  155.19 94.98 270 top
CC1460  1U_0201_6.3V6M  [C_0201]  155.76 94.98 270 top
CC1461  1U_0201_6.3V6M  [C_0201]  156.33 94.98 270 top
CC1462  0.1U_0201_10V6K  [C_0201]  171.13 105.32 90 top
CC1463  1U_0201_6.3V6M  [C_0201]  171.95 95.63 270 top
CC1464  1U_0201_6.3V6M  [C_0201]  185.1 96.21 0 bottom
CC1465  0.33U_0402_10V6K~D  [C_0402]  196.76 75.92 270 top
CC1467  0.33U_0402_10V6K~D  [C_0402]  190.02 75.92 270 top
CC1468  0.33U_0402_10V6K~D  [C_0402]  170.51 80.66 180 top
CC1469  0.33U_0402_10V6K~D  [C_0402]  188.25 75.92 270 top
CC1470  0.33U_0402_10V6K~D  [C_0402]  190.91 75.92 270 top
CC1471  0.33U_0402_10V6K~D  [C_0402]  183.99 75.92 270 top
CC1476  33P_0402_50V8J  [C_0402]  191.27 97.36 180 bottom
CC1477  4.7P_0402_50V8C  [C_0402]  184.67 119.83 180 bottom
CC1478  1200P_0402_50V7K  [C_0402]  138.93 80.64 90 top
CC1479  680P_0402_50V7K  [C_0402]  154.26 80.04 0 top
CC1480  0.1U_0201_10V6K  [C_0201]  168.17 82.62 0 top
CC1481  100P_0201_50V8J  [C_0201]  150.75 118.48 270 bottom
CD1  10U_0603_10V6M  [C_0603]  164.9 54.11 90 top
CD2  10U_0603_10V6M  [C_0603]  158.36 48.02 90 top
CD3  10U_0603_10V6M  [C_0603]  118.07 57.13 180 top
CD4  10U_0603_10V6M  [C_0603]  133.06 56.02 270 top
CD5  10U_0603_10V6M  [C_0603]  104.31 49.54 180 top
CD6  10U_0603_10V6M  [C_0603]  141.16 46.24 90 top
CD7  10U_0603_10V6M  [C_0603]  143.06 46.24 90 top
CD8  10U_0603_10V6M  [C_0603]  115.5 48.59 90 top
CD9  1U_0201_6.3V6M  [C_0201]  109.41 54.9 270 top
CD10  1U_0201_6.3V6M  [C_0201]  121.2 52.41 270 top
CD11  1U_0201_6.3V6M  [C_0201]  133.41 46.99 90 top
CD12  1U_0201_6.3V6M  [C_0201]  135.69 46.99 90 top
CD13  1U_0201_6.3V6M  [C_0201]  124.63 50.42 270 top
CD14  1U_0201_6.3V6M  [C_0201]  158.3 46.3 180 top
CD15  1U_0201_6.3V6M  [C_0201]  128.67 57.2 180 top
CD16  1U_0201_6.3V6M  [C_0201]  128.67 56.18 180 top
CD17  330U_D3_2.5VY_R6M  [C_D3]  117.65 61.51 180 top
CD18  1U_0201_6.3V6M  [C_0201]  168.33 53.5 270 top
CD19  1U_0201_6.3V6M  [C_0201]  167.44 53.5 270 top
CD20  10U_0603_10V6M  [C_0603]  168.33 59.28 180 top
CD21  10U_0603_10V6M  [C_0603]  168.33 58.07 180 top
CD22  10U_0603_10V6M  [C_0603]  242.02 42.1 90 top
CD23  1U_0201_6.3V6M  [C_0201]  243.99 42.27 90 top
CD24  1U_0201_6.3V6M  [C_0201]  243.1 42.27 90 top
CD25  0.1U_0201_6.3V6K  [C_0201]  143.53 43.82 270 top
CD26  2.2U_0402_6.3V6M  [C_0402]  142.57 43.82 270 top
CD27  2.2U_0402_6.3V6M  [C_0402]  166.89 54.94 180 top
CD28  0.1U_0201_10V6K  [C_0201]  166.72 55.7 180 top
CD29  0.1U_0402_25V6  [C_0402]  203.83 43.18 90 top
CD31  0.022U_0402_16V7K  [C_0402]  139.93 43.76 90 top
CD32  0.1U_0201_10V6K  [C_0201]  122.5 75.97 180 top
CD33  10U_0603_10V6M  [C_0603]  197.45 50.05 90 top
CD34  10U_0603_10V6M  [C_0603]  240.6 51.45 270 top
CD35  10U_0603_10V6M  [C_0603]  180.64 44.59 90 top
CD36  10U_0603_10V6M  [C_0603]  217.2 53.24 180 top
CD37  10U_0603_10V6M  [C_0603]  213.45 42.33 90 top
CD38  10U_0603_10V6M  [C_0603]  208.85 42.3 90 top
CD39  10U_0603_10V6M  [C_0603]  235.94 43.51 90 top
CD40  10U_0603_10V6M  [C_0603]  210.75 51.45 270 top
CD41  1U_0201_6.3V6M  [C_0201]  186.79 52.94 180 top
CD42  1U_0201_6.3V6M  [C_0201]  221.75 52.99 0 top
CD43  1U_0201_6.3V6M  [C_0201]  224.46 44.63 90 top
CD44  1U_0201_6.3V6M  [C_0201]  192.76 44.26 90 top
CD45  1U_0201_6.3V6M  [C_0201]  197.92 48.54 270 top
CD46  1U_0201_6.3V6M  [C_0201]  214.9 44.38 90 top
CD47  1U_0201_6.3V6M  [C_0201]  202.32 46.02 90 top
CD48  1U_0201_6.3V6M  [C_0201]  213.23 50.61 270 top
CD49  330U_D3_2.5VY_R6M  [C_D3]  229.38 54.37 0 top
CD50  1U_0201_6.3V6M  [C_0201]  245.27 53.57 90 top
CD51  1U_0201_6.3V6M  [C_0201]  246.87 53.57 90 top
CD52  10U_0603_10V6M  [C_0603]  244.31 53.13 90 top
CD53  10U_0603_10V6M  [C_0603]  243.1 53.13 90 top
CD54  10U_0603_10V6M  [C_0603]  161.16 47.19 270 top
CD55  1U_0201_6.3V6M  [C_0201]  163.89 47 270 top
CD56  1U_0201_6.3V6M  [C_0201]  164.68 47 270 top
CD57  0.1U_0201_6.3V6K  [C_0201]  221.59 42.29 90 top
CD58  2.2U_0402_6.3V6M  [C_0402]  220.7 42.29 90 top
CD59  2.2U_0402_6.3V6M  [C_0402]  247.76 50.37 0 top
CD60  0.1U_0201_10V6K  [C_0201]  247.67 51.13 0 top
CD61  0.1U_0402_25V6  [C_0402]  127.39 46.3 180 top
CD62  0.022U_0402_16V7K  [C_0402]  218.3 43.13 180 top
CD63  10U_0603_10V6M  [C_0603]  159.89 47.19 270 top
CD66  10U_0603_10V6M  [C_0603]  240.82 42.1 90 top
CD69  1U_0201_6.3V6M  [C_0201]  163.1 47 270 top
CD70  1U_0201_6.3V6M  [C_0201]  162.26 47 270 top
CD71  1U_0201_6.3V6M  [C_0201]  244.88 42.27 90 top
CD72  1U_0201_6.3V6M  [C_0201]  245.77 42.27 90 top
CD73  15P_0402_50V8J  [C_0402]  166.87 56.97 180 top
CD74  15P_0402_50V8J  [C_0402]  246.07 53.4 90 top
CD75  10P_0402_50V8J  [C_0402]  246.62 52.35 0 top
CD76  10P_0402_50V8J  [C_0402]  163.63 47.74 90 top
CD77  10P_0402_50V8J  [C_0402]  239.7 42.57 90 top
CE3  2200P_0402_50V7K  [C_0402]  258.63 86.51 270 top
CE4  2200P_0402_50V7K  [C_0402]  255.07 86.51 270 top
CE8  .047U_0402_16V7K  [C_0402]  262.36 103.45 0 top
CE10  0.1U_0201_10V6K  [C_0201]  241.79 94.4 270 bottom
CE11  0.1U_0201_10V6K  [C_0201]  246.12 91.93 270 bottom
CE12  2.2U_0201_6.3V6M  [C_0201]  244.34 94.5 270 bottom
CE13  0.1U_0201_10V6K  [C_0201]  246.67 95.8 270 bottom
CE14  1U_0201_6.3V6M  [C_0201]  246.06 95.81 270 bottom
CE15  0.1U_0201_10V6K  [C_0201]  252.28 91.48 90 bottom
CE16  10U_0402_6.3V6M  [C_0402]  248.29 83.89 180 top
CE17  22U_0603_6.3V6M  [C_0603]  249.97 88.11 0 top
CE18  0.1U_0201_10V6K  [C_0201]  250.33 89.06 0 top
CE19  0.1U_0201_10V6K  [C_0201]  251.01 96.89 270 bottom
CE20  0.1U_0201_10V6K  [C_0201]  252.41 89.27 270 top
CE21  0.1U_0201_10V6K  [C_0201]  259.14 94.09 270 top
CE22  0.1U_0201_10V6K  [C_0201]  262.19 94.09 270 top
CE23  0.1U_0201_10V6K  [C_0201]  255.07 89.27 270 top
CE24  2200P_0402_50V7K  [C_0402]  244.03 96.67 270 top
CE25  0.1U_0201_10V6K  [C_0201]  252.15 102.08 90 bottom
CE26  2200P_0402_50V7K  [C_0402]  244.03 98.45 270 top
CE27  2200P_0402_50V7K  [C_0402]  244.03 100.35 270 top
CE28  10P_0402_50V8J  [C_0402]  242.92 89.28 270 top
CE29  10P_0402_50V8J  [C_0402]  242.92 90.21 90 top
CE30  1U_0201_6.3V6M  [C_0201]  246.86 104.72 180 top
CE31  1U_0201_6.3V6M  [C_0201]  253.17 89.27 270 top
CE32  10U_0402_6.3V6M  [C_0402]  84.96 56.69 0 bottom
CE35  100P_0402_50V8J  [C_0402]  148.65 94.74 90 top
CE36  0.1U_0201_10V6K  [C_0201]  252.53 83.09 90 top
CE37  100P_0402_50V8J  [C_0402]  263.2 31.43 90 bottom
CE38  0.1U_0402_25V6  [C_0402]  247.2 98.32 270 bottom
CE39  100P_0402_50V8J  [C_0402]  121.74 96.81 180 bottom
CE40  4700P_0402_25V7K  [C_0402]  250.76 104.65 90 top
CE46  100P_0402_50V8J  [C_0402]  179.45 38.99 90 bottom
CE47  4700P_0402_25V7K  [C_0402]  259.14 110.51 270 top
CE52  0.1U_0201_10V6K  [C_0201]  253.64 81.1 0 top
CE53  0.1U_0201_10V6K  [C_0201]  269.55 91.09 90 top
CE54  10P_0402_50V8J  [C_0402]  250.35 89.18 270 bottom
CE57  33P_0402_50V8J  [C_0402]  243.64 96.73 270 bottom
CE59  12P_0402_50V8J  [C_0402]  248.29 82.12 180 top
CE60  68P_0402_50V8J  [C_0402]  248.29 83 180 top
CE61  68P_0402_50V8J  [C_0402]  264.73 91.18 90 top
CE62  4700P_0402_25V7K  [C_0402]  246.95 85.75 270 top
CE63  1U_0201_6.3V6M  [C_0201]  247.45 119.53 270 top
CE64  0.1U_0402_25V6  [C_0402]  241.82 120.22 180 top
CE65  22P_0402_50V8J  [C_0402]  243.14 122.83 270 top
CE66  0.1U_0402_25V6  [C_0402]  261.48 97.1 0 top
CE67  0.1U_0402_25V6  [C_0402]  248.39 96.59 0 bottom
CE68  0.1U_0402_25V6  [C_0402]  264.93 97.1 180 top
CE69  2.2U_0201_6.3V6M  [C_0201]  245.26 94.5 270 bottom
CI1  100U_A_6.3VM_R70M  [C_A]  19.87 96.63 270 bottom
CI3  0.1U_0201_10V6K  [C_0201]  21.76 95.16 270 bottom
CI4  0.1U_0402_25V6  [C_0402]  21 90.88 0 bottom
CI5  0.1U_0402_25V6  [C_0402]  21 89.99 0 bottom
CI6  10U_0603_10V6M  [C_0603]  24.82 86.75 90 bottom
CI7  0.1U_0201_10V6K  [C_0201]  25.71 86.9 90 bottom
CI8  100U_A_6.3VM_R70M  [C_A]  299.92 45.93 180 bottom
CI10  0.1U_0201_10V6K  [C_0201]  299.11 52.65 0 top
CI11  10U_0603_10V6M  [C_0603]  299.08 57.48 0 top
CI12  0.1U_0201_10V6K  [C_0201]  299.36 58.43 0 top
CI13  0.1U_0402_25V6  [C_0402]  297.95 66.49 180 bottom
CI14  100U_A_6.3VM_R70M  [C_A]  299.69 63.57 180 bottom
CI16  0.1U_0402_25V6  [C_0402]  297.95 65.61 180 bottom
CI17  0.1U_0201_10V6K  [C_0201]  300.67 60.75 270 top
CI19  0.1U_0201_10V6K  [C_0201]  295.55 71.32 0 top
CI27  0.1U_0402_25V6  [C_0402]  297.95 48.91 180 bottom
CI28  0.1U_0402_25V6  [C_0402]  297.95 48.02 180 bottom
CI29  0.1U_0402_25V6  [C_0402]  260.75 69.73 180 bottom
CI30  0.1U_0402_25V6  [C_0402]  260.75 68.84 180 bottom
CI31  100P_0402_50V8J  [C_0402]  295.51 72.08 0 top
CI32  150U_B2_6.3VM_R35M  [C_B2-NPM]  299.25 60.78 0 bottom
CI33  47U_0603_6.3V6M  [C_0603]  295.4 73.23 0 top
CI34  47U_0603_6.3V6M  [C_0603]  295.4 74.5 0 top
CI43  12P_0402_50V8J  [C_0402]  299.02 60.86 270 top
CI44  68P_0402_50V8J  [C_0402]  299.91 60.86 270 top
CI45  12P_0402_50V8J  [C_0402]  19.87 85.37 270 bottom
CI46  68P_0402_50V8J  [C_0402]  18.85 85.37 270 bottom
CI47  12P_0402_50V8J  [C_0402]  299.47 45.79 180 top
CI48  68P_0402_50V8J  [C_0402]  299.47 46.68 180 top
CI50  18P_0402_50V8J  [C_0402]  298.66 49.92 180 top
CI51  100P_0402_50V8J  [C_0402]  299.47 48.46 180 top
CI52  27P_0402_50V8J  [C_0402]  299.47 47.57 180 top
CI103  150U_B2_6.3VM_R35M  [C_B2-NPM]  19.87 96.32 90 bottom
CI104  150U_B2_6.3VM_R35M  [C_B2-NPM]  299.6 45.93 0 bottom
CL1  0.1U_0402_25V6  [C_0402]  265.16 110.06 0 top
CL2  0.1U_0402_25V6  [C_0402]  265.16 109.17 0 top
CL3  0.1U_0201_10V6K  [C_0201]  273.24 99.55 270 top
CL4  10U_0603_10V6M  [C_0603]  272.34 99.69 270 top
CL5  0.1U_0402_25V6  [C_0402]  265.16 108.28 0 top
CL6  0.1U_0402_25V6  [C_0402]  265.16 107.39 0 top
CL7  0.1U_0201_10V6K  [C_0201]  272.73 112.68 90 top
CL8  0.1U_0201_10V6K  [C_0201]  266.16 105.36 180 top
CL9  0.1U_0201_10V6K  [C_0201]  266.89 111.29 90 top
CL10  0.1U_0201_10V6K  [C_0201]  266.16 105.99 180 top
CL11  0.1U_0201_10V6K  [C_0201]  274.66 103.07 0 top
CL12  22U_0603_6.3V6M  [C_0603]  265.87 111.14 90 top
CL13  27P_0402_50V8J  [C_0402]  274.96 100.02 180 top
CL14  27P_0402_50V8J  [C_0402]  275.83 100.02 0 top
CL16  0.1U_0201_10V6K  [C_0201]  289.55 99.88 0 top
CL17  0.1U_0201_10V6K  [C_0201]  289.55 101.15 0 top
CL18  470P_0402_50V7K  [C_0402]  290.41 112.19 90 top
CL19  0.1U_0201_10V6K  [C_0201]  291.24 112.23 90 top
CL20  0.1U_0201_10V6K  [C_0201]  289.55 107.5 0 top
CL21  0.1U_0201_10V6K  [C_0201]  289.55 108.77 0 top
CL22  10P_1808_3KV8J  [C_1808]  291.28 94.18 0 bottom
CL28  22U_0603_6.3V6M  [C_0603]  270.57 102.14 270 top
CL29  100P_0402_50V8J  [C_0402]  273.49 112.77 90 top
CL30  100P_0402_50V8J  [C_0402]  269.17 102.13 270 top
CMOS1  SHORT PADS~D  [SHORTPADS-NPM]  206.69 75.32 270 top
CN1  10U_0603_10V6M  [C_0603]  249.68 32.2 180 top
CN2  0.1U_0201_10V6K  [C_0201]  249.02 36.4 180 top
CN3  0.1U_0201_10V6K  [C_0201]  249.7 36.4 0 top
CN4  0.01UF_0402_25V7K  [C_0402]  250.69 41.97 90 bottom
CN5  0.01UF_0402_25V7K  [C_0402]  251.58 41.97 90 bottom
CN6  0.01UF_0402_25V7K  [C_0402]  252.47 41.97 90 bottom
CN7  0.01UF_0402_25V7K  [C_0402]  253.36 41.97 90 bottom
CN8  1000P_0402_50V7K  [C_0402]  258.63 36.32 90 bottom
CN9  0.1U_0201_10V6K  [C_0201]  257.88 36.74 90 bottom
CN10  0.1U_0201_10V6K  [C_0201]  248.13 40.21 180 top
CN11  0.1U_0201_10V6K  [C_0201]  248.13 40.78 180 top
CN12  0.01UF_0402_25V7K  [C_0402]  254.57 53.64 270 bottom
CN13  0.01UF_0402_25V7K  [C_0402]  255.46 53.64 270 bottom
CN14  0.01UF_0402_25V7K  [C_0402]  256.34 53.64 270 bottom
CN15  0.01UF_0402_25V7K  [C_0402]  257.23 53.64 270 bottom
CN16  0.01UF_0402_25V7K  [C_0402]  259.95 45.41 0 bottom
CN17  0.1U_0201_10V6K  [C_0201]  253.3 52.04 90 bottom
CN60  68P_0402_50V8J  [C_0402]  278.87 23.1 90 top
CN61  0.1U_0402_10V7K  [C_0402]  267.88 24.22 0 top
CN62  0.1U_0402_10V7K  [C_0402]  277.93 23.1 90 top
CN63  22U_0603_6.3V6M  [C_0603]  279.96 23.12 90 top
CN64  22U_0603_6.3V6M  [C_0603]  282.1 23.05 90 top
CN65  0.22U_0402_10V6K  [C_0402]  280.74 28.27 90 top
CN66  0.22U_0402_10V6K  [C_0402]  279.86 28.27 90 top
CN67  0.22U_0402_10V6K  [C_0402]  277.32 28.27 90 top
CN68  0.22U_0402_10V6K  [C_0402]  276.43 28.27 90 top
CN69  0.22U_0402_10V6K  [C_0402]  273.89 28.27 90 top
CN70  0.22U_0402_10V6K  [C_0402]  273 28.27 90 top
CN71  0.22U_0402_10V6K  [C_0402]  270.46 28.27 90 top
CN72  0.22U_0402_10V6K  [C_0402]  269.57 28.27 90 top
CN75  27P_0402_50V8J  [C_0402]  249.56 31.06 180 top
CN77  22U_0603_6.3V6M  [C_0603]  267.62 25.32 0 top
CN78  100P_0402_50V8J  [C_0402]  257.13 36.31 90 bottom
CN79  0.01U_0402_16V7K  [C_0402]  262.67 21.26 180 top
CN80  0.01U_0402_16V7K  [C_0402]  277.03 23.09 90 top
CN81  0.01U_0402_16V7K  [C_0402]  262.67 22.17 180 top
CN82  0.01U_0402_16V7K  [C_0402]  282.34 21 0 top
CN84  0.01U_0402_16V7K  [C_0402]  265.13 25.46 180 top
CN86  0.1U_0402_10V7K  [C_0402]  281.03 23.21 90 top
CN87  22P_0402_50V8J  [C_0402]  261.6 34.76 135 top
CN88  82P_0402_50V8J  [C_0402]  263.21 35.79 135 top
CN89  100P_0402_50V8J  [C_0402]  263.62 37.14 135 top
CN90  82P_0402_50V8J  [C_0402]  268.04 38.81 0 top
CN91  0.1U_0402_10V7K  [C_0402]  268.04 40.63 0 top
CN92  47P_0402_50V8J  [C_0402]  264.99 39.65 180 top
CN93  22P_0402_50V8J  [C_0402]  265.02 38.75 180 top
CN94  1U_0402_25V6K  [C_0402]  265.01 40.56 180 top
CN95  220P_0402_50V7K  [C_0402]  268.03 39.72 0 top
CR1  4.7U_0402_6.3V6M  [C_0402]  290.79 29.03 90 top
CR2  0.1U_0201_10V6K  [C_0201]  291.61 27.56 0 top
CR3  0.1U_0201_10V6K  [C_0201]  289.58 18.51 90 top
CR4  10U_0402_6.3V6M  [C_0402]  288.68 18.17 180 top
CR5  4.7U_0402_6.3V6M  [C_0402]  291.83 19.12 0 top
CR6  0.1U_0201_10V6K  [C_0201]  288.2 20.14 180 top
CR7  0.1U_0201_10V6K  [C_0201]  291.74 19.89 0 top
CR11  0.1U_0402_25V6  [C_0402]  285.5 25.23 0 top
CR12  0.1U_0402_25V6  [C_0402]  285.5 24.34 0 top
CR13  0.1U_0402_25V6  [C_0402]  285.5 22.82 0 top
CR14  0.1U_0402_25V6  [C_0402]  285.5 21.93 0 top
CR15  1U_0201_6.3V6M  [C_0201]  293.99 26.15 270 top
CR17  0.1U_0201_10V6K  [C_0201]  302.13 18.58 90 top
CR18  10U_0402_6.3V6M  [C_0402]  301.37 18.29 90 top
CR19  0.1U_0201_10V6K  [C_0201]  301.68 26.78 270 top
CR20  10U_0402_6.3V6M  [C_0402]  300.92 27.01 270 top
CR21  5P_0402_50V8C  [C_0402]  295.89 20.39 0 top
CR22  1U_0201_6.3V6M  [C_0201]  294.79 22.04 0 top
CR25  12P_0201_50V8J  [C_0201]  290.72 18.51 90 top
CR26  82P_0201_50V8J  [C_0201]  290.14 18.51 90 top
CR27  12P_0201_50V8J  [C_0201]  291.61 28.19 0 top
CR28  82P_0201_50V8J  [C_0201]  291.61 28.83 0 top
CT22  100P_0402_50V8J~D  [C_0402]  66.15 99.64 0 top
CT44  0.1U_0402_25V6  [C_0402]  40.01 109.17 180 top
CT45  0.1U_0402_25V6  [C_0402]  37.51 103.45 0 top
CT46  0.01UF_0402_25V7K  [C_0402]  37.51 104.34 0 top
CT47  0.1U_0402_25V6  [C_0402]  40.88 109.17 0 top
CT48  0.01UF_0402_25V7K  [C_0402]  40.01 110.06 180 top
CT70  .1U_0402_16V7K  [C_0402]  38.54 89.66 90 bottom
CT71  2.2U_0402_25V6K  [C_0402]  54.82 102.59 180 bottom
CT72  2.2U_0402_25V6K  [C_0402]  57.86 100.24 180 bottom
CT73  2.2U_0402_25V6K  [C_0402]  56.21 107.67 180 bottom
CT74  10U_0402_6.3V6M  [C_0402]  55.37 100.57 270 bottom
CT75  22U_0805_25V6M  [C_0805]  65.63 101.04 0 top
CT76  22U_0805_25V6M  [C_0805]  65.63 102.82 0 top
CT77  22U_0805_25V6M  [C_0805]  65.63 101.04 0 bottom
CT78  22U_0805_25V6M  [C_0805]  65.63 102.82 0 bottom
CT80  0.1U_0201_10V6K  [C_0201]  52.92 106.59 0 bottom
CT81  0.1U_0201_10V6K  [C_0201]  52.92 107.23 0 bottom
CT82  1U_0402_25V6K  [C_0402]  63.19 108.91 180 top
CT83  1U_0201_6.3V6M  [C_0201]  56.02 106.08 180 bottom
CT84  10U_0402_6.3V6M  [C_0402]  54.61 104.56 180 bottom
CT85  220P_0402_50V8J  [C_0402]  63.81 110.72 0 bottom
CT86  220P_0402_50V8J  [C_0402]  62.74 110.71 90 bottom
CT87  0.22U_0402_16V7K  [C_0402]  60.82 106.53 0 top
CT88  0.1U_0201_10V6K  [C_0201]  58.35 122.08 90 top
CT89  1U_0201_10V6M  [C_0201]  57.72 122.08 90 top
CT90  1U_0201_10V6M  [C_0201]  55.65 122.88 0 top
CT91  2.2U_0402_10V6M  [C_0402]  57.04 116.98 0 top
CT92  0.1U_0402_25V6K  [C_0402]  57.04 116.1 0 top
CT93  1U_0201_10V6M  [C_0201]  63.56 122.15 90 top
CT94  1U_0402_25V6K  [C_0402]  64.04 113.37 90 top
CT99  0.01U_0201_25V6K  [C_0201]  9.99 105.42 0 top
CT100  0.01U_0201_25V6K  [C_0201]  10.57 108.09 180 top
CT101  0.01U_0201_25V6K  [C_0201]  9.99 108.66 0 top
CT102  0.01U_0201_25V6K  [C_0201]  10.57 105.99 180 top
CT103  0.22U_0402_10V6K  [C_0402]  46.3 104.66 180 bottom
CT104  0.22U_0402_10V6K  [C_0402]  46.3 103.77 180 bottom
CT105  0.22U_0402_10V6K  [C_0402]  46.3 102.88 180 bottom
CT106  0.22U_0402_10V6K  [C_0402]  46.3 101.99 180 bottom
CT107  0.22U_0402_10V6K  [C_0402]  46.3 101.1 180 bottom
CT108  0.22U_0402_10V6K  [C_0402]  46.3 100.21 180 bottom
CT109  0.22U_0402_10V6K  [C_0402]  46.3 99.32 180 bottom
CT110  0.22U_0402_10V6K  [C_0402]  46.3 98.44 180 bottom
CT111  0.22U_0402_10V6K  [C_0402]  46.3 108.21 180 bottom
CT112  0.22U_0402_10V6K  [C_0402]  46.3 107.33 180 bottom
CT113  0.22U_0402_10V6K  [C_0402]  46.3 106.44 180 bottom
CT114  0.22U_0402_10V6K  [C_0402]  46.3 105.55 180 bottom
CT115  0.1U_0402_25V6  [C_0402]  40.76 96.71 90 bottom
CT116  0.1U_0402_25V6  [C_0402]  39.87 96.71 90 bottom
CT117  4.7U_0402_6.3V6M  [C_0402]  38.1 106.13 270 top
CT118  0.1U_0201_10V6K  [C_0201]  41.82 100.34 180 top
CT119  1U_0201_6.3V6M  [C_0201]  36.13 107.22 90 bottom
CT122  1U_0201_6.3V6M  [C_0201]  36.04 101.99 180 bottom
CT189  12P_0402_50V8J  [C_0402]  19.88 97.86 180 top
CT190  82P_0402_50V8J  [C_0402]  19.88 96.97 180 top
CT326  0.33U_0201_25V6K  [C_0201]  14.01 103.92 180 top
CT327  0.33U_0201_25V6K  [C_0201]  14.01 104.56 180 top
CT328  0.33U_0201_25V6K  [C_0201]  15.09 107.58 180 bottom
CT329  0.33U_0201_25V6K  [C_0201]  15.09 106.95 180 bottom
CT610  0.01UF_0402_25V7K  [C_0402]  40.88 108.28 0 top
CT611  0.1U_0402_25V6  [C_0402]  43.57 107.83 180 top
CT612  0.01UF_0402_25V7K  [C_0402]  43.57 106.06 180 top
CT614  0.1U_0402_25V6  [C_0402]  37.65 108.96 90 bottom
CT615  0.01UF_0402_25V7K  [C_0402]  40.52 100.21 180 top
CT616  0.01UF_0402_25V7K  [C_0402]  37.51 101.1 0 top
CT617  0.1U_0402_25V6  [C_0402]  38.54 108.96 90 bottom
CT618  0.1U_0402_25V6  [C_0402]  42.16 108.96 90 bottom
CT625  4.7U_0402_6.3V6M  [C_0402]  40.01 108.28 180 top
CT626  4.7U_0402_6.3V6M  [C_0402]  37.51 102.56 0 top
CT627  4.7U_0402_6.3V6M  [C_0402]  43.57 106.94 180 top
CT628  4.7U_0402_6.3V6M  [C_0402]  42.87 103.45 180 top
CT629  4.7U_0402_6.3V6M  [C_0402]  40.88 110.06 0 top
CT634  0.22U_0201_25V6K  [C_0201]  14 103.96 180 bottom
CT635  0.22U_0201_25V6K  [C_0201]  14 104.53 180 bottom
CT636  0.22U_0201_25V6K  [C_0201]  15.15 107.58 180 top
CT637  0.22U_0201_25V6K  [C_0201]  15.15 106.94 180 top
CV1  0.1U_0402_25V6  [C_0402]  151.25 122.55 90 bottom
CV2  0.1U_0402_25V6  [C_0402]  150.36 122.55 90 bottom
CV3  0.1U_0402_25V6  [C_0402]  147.31 120.65 90 bottom
CV4  0.1U_0402_25V6  [C_0402]  148.2 120.65 90 bottom
CV5  0.1U_0402_25V6  [C_0402]  149.28 120.65 90 bottom
CV6  0.1U_0402_25V6  [C_0402]  150.17 120.65 90 bottom
CV11  0.1U_0603_50V7K  [C_0603]  135.01 131.46 270 top
CV12  100P_0201_50V8J  [C_0201]  141.79 131.3 270 top
CV13  1000P_0402_50V7K  [C_0402]  129.09 135.28 270 top
CV14  0.01U_0402_50V7K  [C_0402]  127.39 134.31 180 top
CV15  0.1U_0402_25V6  [C_0402]  134.62 136.22 0 top
CV16  100P_0402_50V8J  [C_0402]  144.84 134.62 90 top
CV17  0.01UF_0402_25V7K  [C_0402]  154.62 136.04 270 top
CV18  12P_0402_50V8J  [C_0402]  124.34 131.75 0 top
CV19  82P_0402_50V8J  [C_0402]  124.35 130.83 0 top
CV20  12P_0402_50V8J  [C_0402]  143.06 134.62 90 top
CV21  82P_0402_50V8J  [C_0402]  143.95 134.62 90 top
CV22  12P_0402_50V8J  [C_0402]  127.86 130.1 180 top
CV23  82P_0402_50V8J  [C_0402]  127.85 129.14 180 top
CV24  12P_0402_50V8J  [C_0402]  133.92 131.47 270 top
CV25  82P_0402_50V8J  [C_0402]  133.03 131.47 270 top
CV26  0.1U_0201_10V6K  [C_0201]  303.46 81.95 90 bottom
CV27  10U_0402_6.3V6M  [C_0402]  302.57 81.29 90 bottom
CV31  100P_0201_50V8J  [C_0201]  127.81 131.46 180 top
CV54  33P_0402_50V8J  [C_0402]  118.98 120.47 0 top
CV55  33P_0402_50V8J  [C_0402]  117.48 120.47 180 top
CV300  0.1U_0402_10V7K  [C_0402]  289.7 83.58 180 top
CV301  0.1U_0402_10V7K  [C_0402]  289.7 82.69 180 top
CV302  0.1U_0402_10V7K  [C_0402]  289.7 91.39 180 top
CV303  0.1U_0402_10V7K  [C_0402]  289.7 90.5 180 top
CV304  0.1U_0402_10V7K  [C_0402]  289.7 93.16 180 top
CV305  0.1U_0402_10V7K  [C_0402]  289.7 92.28 180 top
CV306  0.1U_0402_10V7K  [C_0402]  289.7 81.8 180 top
CV307  0.1U_0402_10V7K  [C_0402]  289.7 80.91 180 top
CV308  0.01U_0402_16V7K  [C_0402]  291.46 80.92 270 top
CV309  0.1U_0402_25V6  [C_0402]  294.37 90.9 90 top
CV310  0.01U_0402_16V7K  [C_0402]  297.87 81.87 270 top
CV311  0.1U_0402_25V6  [C_0402]  292.25 90.92 90 top
CV312  0.1U_0402_25V6  [C_0402]  298.46 90.37 0 top
CV313  0.1U_0402_25V6  [C_0402]  292.92 81.43 270 top
CV314  0.1U_0402_25V6  [C_0402]  298.76 81.87 270 top
CV632  0.1U_0402_25V6  [C_0402]  97.14 126.57 0 top
CV633  2200P_0402_50V7K  [C_0402]  96.58 135.91 270 top
CV634  0.1U_0402_25V6  [C_0402]  136.08 131.28 270 top
CV635  0.1U_0402_25V6K  [C_0402]  118.26 135.23 90 top
CV651  2200P_0402_50V7K  [C_0402]  144.03 129.36 180 top
CV652  0.1U_0402_25V6  [C_0402]  142.55 131.47 270 top
CV653  0.1U_0201_10V6K  [C_0201]  297.75 82.33 90 bottom
CV755  47P_0402_50V8J  [C_0402]  94.86 132.97 90 top
CV756  100P_0402_50V8J~D  [C_0402]  95.82 132.97 90 top
CV757  100P_0201_50V8J  [C_0201]  136.84 131.3 270 top
CZ3  100P_0402_50V8J  [C_0402]  96.66 131.01 270 bottom
CZ10  0.1U_0402_25V6  [C_0402]  266.89 69.4 90 bottom
CZ11  0.1U_0402_25V6  [C_0402]  267.77 69.4 90 bottom
CZ12  0.1U_0402_25V6  [C_0402]  266.19 34.44 270 bottom
CZ13  0.1U_0402_25V6  [C_0402]  265.3 34.44 270 bottom
CZ17  1U_0201_6.3V6M  [C_0201]  279.13 82.37 0 top
CZ18  22U_0402_6.3V6M  [C_0402]  279.13 83.26 0 top
CZ19  0.1U_0402_25V6  [C_0402]  279.13 81.48 0 top
CZ20  100U_B2_6.3VM_R35M  [C_B2]  256.26 79.58 0 bottom
CZ21  100P_0402_50V8J  [C_0402]  258 82.57 270 top
CZ23  8.2P_0402_50V8D  [C_0402]  259.77 82.57 270 top
CZ24  18P_0402_50V8J  [C_0402]  258.88 82.57 270 top
CZ25  100P_0402_50V8J  [C_0402]  279.13 84.15 0 top
CZ26  100P_0402_50V8J  [C_0402]  257.11 82.57 270 top
CZ27  10U_0603_10V6M  [C_0603]  270 41.09 270 top
CZ28  0.01UF_0402_25V7K  [C_0402]  271.2 41.04 270 top
CZ29  0.01UF_0402_25V7K  [C_0402]  290.63 40.64 90 top
CZ30  0.1U_0201_10V6K  [C_0201]  270.1 45.54 180 top
CZ31  0.1U_0201_10V6K  [C_0201]  289.87 40.8 90 top
CZ32  10U_0402_6.3V6M  [C_0402]  291.52 40.64 90 top
CZ33  100P_0402_50V8J  [C_0402]  270.26 43 180 top
CZ34  100P_0402_50V8J  [C_0402]  270.26 42.11 180 top
CZ35  15P_0402_50V8J  [C_0402]  270.26 44.78 180 top
CZ36  15P_0402_50V8J  [C_0402]  270.26 43.89 180 top
CZ37  4.7U_0402_6.3V6M  [C_0402]  301.63 23.63 180 top
CZ38  47P_0402_50V8J  [C_0402]  298.59 21.28 180 top
CZ39  33P_0402_50V8J  [C_0402]  298.59 22.17 180 top
CZ40  33P_0402_50V8J  [C_0402]  298.59 19.5 180 top
CZ41  0.1U_0402_25V6  [C_0402]  301.63 24.52 180 top
CZ50  0.1U_0201_10V6K  [C_0201]  227.77 104.75 90 top
CZ51  0.1U_0201_10V6K  [C_0201]  229 98.44 0 top
CZ52  10U_0402_6.3V6M  [C_0402]  228.96 97.67 0 top
CZ53  0.1U_0201_10V6K  [C_0201]  224.21 104.75 90 top
CZ54  0.1U_0201_10V6K  [C_0201]  220.82 99.07 270 top
CZ55  10U_0603_10V6M  [C_0603]  219.93 98.97 270 top
CZ56  0.1U_0402_25V6  [C_0402]  218.7 101.86 180 top
CZ57  12P_0402_50V8J  [C_0402]  239.64 63.95 180 top
CZ58  68P_0402_50V8J  [C_0402]  243.54 64.22 0 top
CZ62  68P_0402_50V8J  [C_0402]  230.93 36.92 270 top
CZ63  68P_0402_50V8J  [C_0402]  230.04 36.92 270 top
CZ64  0.1U_0201_10V6K  [C_0201]  228.67 40.08 90 top
CZ66  0.1U_0201_10V6K  [C_0201]  227.17 40.38 90 top
CZ67  0.1U_0201_10V6K  [C_0201]  227.68 36.7 180 top
CZ68  0.1U_0201_10V6K  [C_0201]  230.75 40.05 90 top
CZ69  68P_0402_50V8J  [C_0402]  227.94 39.94 90 top
CZ71  68P_0402_50V8J  [C_0402]  225.84 40.12 90 top
CZ72  68P_0402_50V8J  [C_0402]  228.14 35.29 180 top
CZ73  68P_0402_50V8J  [C_0402]  229.99 39.94 90 top
CZ75  10U_0402_6.3V6M  [C_0402]  226.88 104.71 90 top
CZ80  10P_0402_50V8J  [C_0402]  193.42 36.9 90 top
CZ81  10P_0402_50V8J  [C_0402]  191 36.9 90 top
CZ82  0.1U_0201_10V6K  [C_0201]  269.04 94.98 270 top
CZ83  68P_0402_50V8J  [C_0402]  188.08 36.73 270 top
CZ84  68P_0402_50V8J  [C_0402]  183.57 39.88 90 top
CZ85  68P_0402_50V8J  [C_0402]  186.49 39.88 90 top
CZ86  68P_0402_50V8J  [C_0402]  187.38 39.88 90 top
CZ87  68P_0402_50V8J  [C_0402]  188.27 39.88 90 top
CZ88  68P_0402_50V8J  [C_0402]  189.16 39.88 90 top
CZ89  68P_0402_50V8J  [C_0402]  190.05 39.88 90 top
CZ90  0.1U_0201_10V6K  [C_0201]  188.84 36.62 270 top
CZ91  0.1U_0201_10V6K  [C_0201]  185.73 39.91 90 top
CZ92  0.1U_0201_10V6K  [C_0201]  185.1 39.91 90 top
CZ93  0.1U_0201_10V6K  [C_0201]  309.18 7.61 270 top
CZ100  1U_0201_6.3V6M  [C_0201]  193.35 128.38 270 top
CZ101  0.1U_0201_10V6K  [C_0201]  198.94 132.94 90 top
CZ102  1U_0201_6.3V6M  [C_0201]  168.57 65.12 270 top
CZ105  1U_0201_6.3V6M  [C_0201]  193.35 130.21 90 top
CZ106  0.1U_0201_10V6K  [C_0201]  193.1 132.12 0 top
CZ109  470P_0402_50V7K  [C_0402]  275.85 91.07 180 top
CZ110  470P_0402_50V7K  [C_0402]  275.85 91.96 180 top
CZ112  0.1U_0201_10V6K  [C_0201]  223.58 82.54 270 top
CZ113  100P_0402_50V8J  [C_0402]  222.89 84.66 180 top
CZ114  1000P_0402_50V7K  [C_0402]  222.89 85.54 180 top
CZ115  0.1U_0201_10V6K  [C_0201]  224.75 87.26 0 top
CZ116  0.1U_0201_10V6K  [C_0201]  269.68 63.66 270 top
CZ117  470P_0402_50V7K  [C_0402]  268.85 63.99 270 top
CZ118  470P_0402_50V7K  [C_0402]  267.94 63.99 270 top
CZ119  0.1U_0201_10V6K  [C_0201]  275.43 89.23 180 top
CZ120  0.1U_0201_10V6K  [C_0201]  278.4 64.21 0 top
CZ121  470P_0402_50V7K  [C_0402]  275.73 63.32 180 top
CZ122  0.1U_0201_10V6K  [C_0201]  266.38 66.33 90 top
CZ124  2200P_0402_50V7K  [C_0402]  275.85 89.99 180 top
CZ125  0.1U_0201_10V6K  [C_0201]  271.9 56.31 270 top
CZ126  220P_0402_50V7K  [C_0402]  271.14 56.22 270 top
CZ127  1000P_0402_50V7K  [C_0402]  270.25 56.22 270 top
